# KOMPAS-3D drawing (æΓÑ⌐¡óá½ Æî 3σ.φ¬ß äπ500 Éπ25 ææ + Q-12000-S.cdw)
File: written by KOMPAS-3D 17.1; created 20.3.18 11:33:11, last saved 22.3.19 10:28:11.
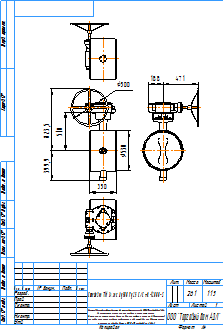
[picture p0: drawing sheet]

Sheet 1: A4, portrait

Title block, sheet 1: name: Стейнвал ТМ 3х.экс Ду500 Ру25 С/С + Q-12000-S; mass: 261; sheets: 1; sheet format: A4; stored path: C:\Users\kka\KOMPAS_Work\Дисковые повортные затворы ф. Boteli\Стейнвал + редуктор-привода\Стейнвал ТМ 3х.экс Ду500 Ру25 СС + Q-12000-S.cdw

Views: Проекционный вид 2, Проекционный вид 3, Проекционный вид 4
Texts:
  kka
  adl
  Рама для чертежей
  Лит-Масса-Масштаб
  Материал-Предприятие
  Масштаб
  Изм.
  Лист
  № докум.
  Подп.
  Дата
  Лит.
  Разраб.
  Пров.
  Т.контр.
  Листов
  Внимание! Данный продукт является объектом авторского права ООО «Торговый Дом АДЛ».
  Запрещается изменение, копирование, распространение
  (в том числе путем копирования на другие сайты и ресурсы в Интернете)
  или любое иное использование информации и объектов без предварительного
  согласия правообладателя (ООО «Торговый Дом АДЛ»).
  Н.контр.
  Утв.
  ООО "Торговый дом АДЛ"
  Изменение
  Номер документа
  Подпись
  Обозначение документа
  Наименование изделия
  Масса изделия по ГОСТ 2.109-73
  Порядковый номер листа
  Общее количество листов в документе
  Характер работы, выполненной лицом, подписавшим документ
  Наименование или индекс предприятия, выпускающего документ
  Инв. № подл.
  Подп. и дата
  Взам. инв. №
  Инв. № дубл.
  Инвентарный номер подлинника по ГОСТ 2.501-68
  Подпись принявшего подлинник в отдел технической документации
  Инвентарный номер подлинника, взамен которого выпущен данный подлинник
  Инвентарный номер дубликата по ГОСТ 2.502-68
  Подпись принявшего дубликат в отдел технической документации
  Справ. №
  Перв. примен.
  Обозначение документа, взамен или на основании которого выпущен данный документ
  Обозначение документа, в котором впервые записан данный документ
  Подпись лица, копировавшего чертеж
  Обозначение формата листа
  !Рама для чертежа
Dimensions and other numbers on the sheet: 471; 188; 1:15; 1; 261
